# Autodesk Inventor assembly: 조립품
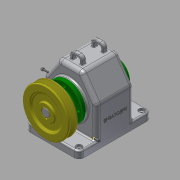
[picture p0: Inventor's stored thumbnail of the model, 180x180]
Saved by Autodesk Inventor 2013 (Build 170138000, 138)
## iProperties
Created: 2016-12
Part Number: 조립품
Document SubType Name: Assembly
Designer: Administrator
Author: Administrator
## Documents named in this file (15)
- C:\Users\Administrator\Desktop\461207V1001\조립품.iam
- C:\Users\Administrator\Desktop\461207V1001\본체.ipt
- C:\Users\Administrator\Desktop\461207V1001\461207V1001\V-벨트풀리.ipt
- C:\Users\Administrator\Desktop\461207V1001\461207V1001\뒤커버.ipt
- C:\Users\Administrator\Desktop\461207V1001\461207V1001\멈춤나사 - M4x10.ipt
- C:\Users\Administrator\Desktop\461207V1001\461207V1001\베어링 6203.ipt
- C:\Users\Administrator\Desktop\461207V1001\461207V1001\볼트 M3 x 8.ipt
- C:\Users\Administrator\Desktop\461207V1001\461207V1001\볼트 M3 x 10.ipt
- C:\Users\Administrator\Desktop\461207V1001\461207V1001\부시.ipt
- C:\Users\Administrator\Desktop\461207V1001\461207V1001\스퍼기어.ipt
- C:\Users\Administrator\Desktop\461207V1001\461207V1001\앞커버.ipt
- C:\Users\Administrator\Desktop\461207V1001\461207V1001\오일씰 28 40 8.ipt
- C:\Users\Administrator\Desktop\461207V1001\461207V1001\축.ipt
- C:\Users\Administrator\Desktop\461207V1001\461207V1001\키 - 5 x 5 x 18.ipt
- C:\Users\Administrator\Desktop\461207V1001\461207V1001\키 - 6 x 6 x 22.ipt
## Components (6 placed, 3 different names)
1. V-벨트풀리:1 — 플러쉬:1
2. ISO 4762 M3 x 8:1
3. ISO 4762 M3 x 10:1
4. ISO 4762 M3 x 8:2
5. ISO 4762 M3 x 8:3
6. ISO 4762 M3 x 8:4
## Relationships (1: Flush 1)
- 플러쉬:1 [Flush]: V-벨트풀리:1
